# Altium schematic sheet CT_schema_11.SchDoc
size 297 x 239 mm
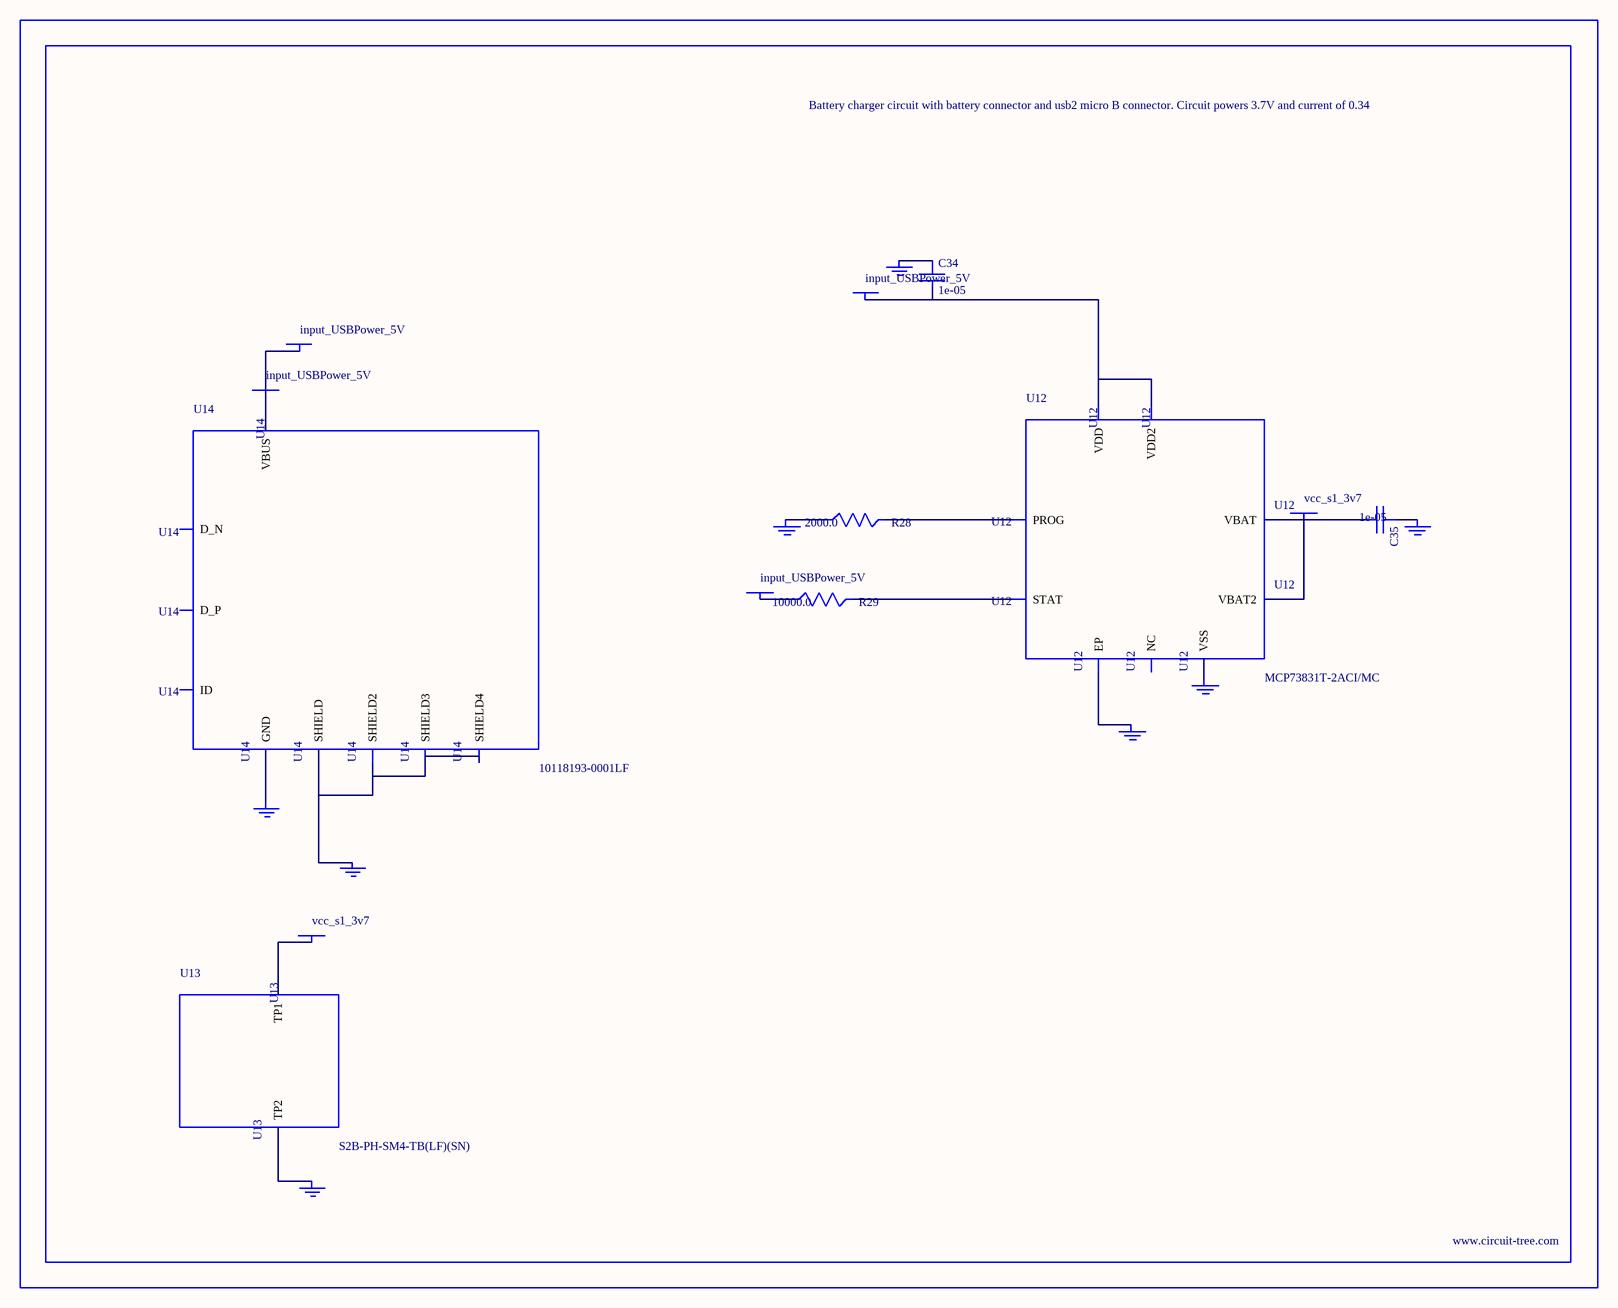
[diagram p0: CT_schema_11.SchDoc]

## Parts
BORDER10  (no value)
C34  1e-05  [C1206]
C35  1e-05  [C1206]
GND_INSTANCE_10_0  (no value)
GND_INSTANCE_10_1  (no value)
GND_INSTANCE_10_2  (no value)
GND_INSTANCE_10_3  (no value)
GND_INSTANCE_10_4  (no value)
GND_INSTANCE_10_5  (no value)
GND_INSTANCE_10_6  (no value)
GND_INSTANCE_10_7  (no value)
POWER_INSTANCE_10_0  input_USBPower_5V
POWER_INSTANCE_10_1  input_USBPower_5V
POWER_INSTANCE_10_2  vcc_s1_3v7
POWER_INSTANCE_10_3  vcc_s1_3v7
POWER_INSTANCE_10_4  input_USBPower_5V
POWER_INSTANCE_10_5  input_USBPower_5V
R28  2000.0  [R0603]
R29  10000.0  [R0603]
U12  MCP73831T-2ACI/MC  [DFN8_2X3MC]
U13  S2B-PH-SM4-TB(LF)(SN)  [JST-2-SMD]
U14  10118193-0001LF  [FCI_10118193-0001LF]

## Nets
NetC34_1: C34.1 GND_INSTANCE_10_0.0(GND)
NetC34_2: C34.2 POWER_INSTANCE_10_0.0(PWR) U12.1(VDD) U12.2(VDD2)
NetC35_1: C35.1 GND_INSTANCE_10_1.0(GND)
NetC35_2: C35.2 POWER_INSTANCE_10_2.0(PWR) U12.3(VBAT) U12.4(VBAT2)
NetGND_INSTANCE_10_2_0: GND_INSTANCE_10_2.0(GND) R28.1
NetGND_INSTANCE_10_3_0: GND_INSTANCE_10_3.0(GND) U12.9(EP)
NetGND_INSTANCE_10_4_0: GND_INSTANCE_10_4.0(GND) U12.6(VSS)
NetGND_INSTANCE_10_5_0: GND_INSTANCE_10_5.0(GND) U13.2(TP2)
NetGND_INSTANCE_10_6_0: GND_INSTANCE_10_6.0(GND) U14.6(SHIELD) U14.7(SHIELD2) U14.8(SHIELD3) U14.9(SHIELD4)
NetGND_INSTANCE_10_7_0: GND_INSTANCE_10_7.0(GND) U14.5(GND)
NetPOWER_INSTANCE_10_1_0: POWER_INSTANCE_10_1.0(PWR) R29.1
NetPOWER_INSTANCE_10_3_0: POWER_INSTANCE_10_3.0(PWR) U13.1(TP1)
NetPOWER_INSTANCE_10_4_0: POWER_INSTANCE_10_4.0(PWR) POWER_INSTANCE_10_5.0(PWR) U14.1(VBUS)
NetR28_2: R28.2 U12.8(PROG)
NetR29_2: R29.2 U12.5(STAT)

Not connected (* = marked no-connect by the designer): U12 7(NC); U14 2(D_N) 3(D_P) 4(ID)

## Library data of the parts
BORDER10 = BORDER_PAGE10
C34 C35 = C1206C106K3RACTU
GND_INSTANCE_10_0-GND_INSTANCE_10_7 = GND
POWER_INSTANCE_10_0-POWER_INSTANCE_10_5 = PWR
R28 = RC0603JR-072KL
R29 = RC0603JR-0710KL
